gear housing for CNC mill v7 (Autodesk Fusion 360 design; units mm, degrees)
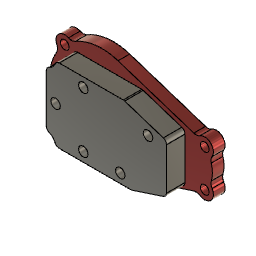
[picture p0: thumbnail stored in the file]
description: Gear Housing Assembly
derived_base_feature "Derived Base Feature1"
derived_base_feature "Derived Base Feature1" bodies "Front Housing"
derived_base_feature "Derived Base Feature1" bodies "Front Cover"
derived_base_feature "Derived Base Feature1" bodies "Back Housing"
as_built_joint "As-built1"
offset_faces "OffsetFaces1" distance 5
delete_face "DeleteFace1"
delete_face "DeleteFace2"
sketch "Sketch1" plane through (0, -21, 0) normal (0, -1, 0) x axis (1, 0, 0)
  line L1 (11.1724, 34.2225) -> (63.2283, 17.2281)
  line L2 (63.2283, -17.2281) -> (11.1724, -34.2225)
  arc A1 centre (64.7801, 21.9812) radius 5 clockwise from (67.4836, 17.7752) to (63.2283, 17.2281)
  arc A2 centre (0, 0) radius 36 clockwise from (-18.189, 31.067) to (11.1724, 34.2225)
  arc A3 centre (-20.7152, 35.3819) radius 5 clockwise from (-18.189, 31.067) to (-22.8701, 30.8701)
  arc A4 centre (-25.4558, 25.4558) radius 6 clockwise from (-30.8701, 22.8701) to (-22.8701, 30.8701)
  arc A5 centre (-35.3819, 20.7152) radius 5 clockwise from (-30.8701, 22.8701) to (-31.067, 18.189)
  arc A6 centre (0, 0) radius 36 clockwise from (-31.067, -18.189) to (-31.067, 18.189)
  arc A7 centre (-35.3819, -20.7152) radius 5 clockwise from (-31.067, -18.189) to (-30.8701, -22.8701)
  arc A8 centre (-25.4558, -25.4558) radius 6 clockwise from (-22.8701, -30.8701) to (-30.8701, -22.8701)
  arc A9 centre (-20.7152, -35.3819) radius 5 clockwise from (-22.8701, -30.8701) to (-18.189, -31.067)
  arc A10 centre (0, 0) radius 36 clockwise from (11.1724, -34.2225) to (-18.189, -31.067)
  arc A11 centre (64.7801, -21.9812) radius 5 clockwise from (63.2283, -17.2281) to (67.4836, -17.7752)
  arc A12 centre (70.7279, -12.7279) radius 6 clockwise from (75.774, -9.4818) to (67.4836, -17.7752)
  arc A13 centre (79.979, -6.7767) radius 5 clockwise from (75.774, -9.4818) to (75.201, -5.3035)
  arc A14 centre (58, 0) radius 18 clockwise from (75.201, 5.3035) to (75.201, -5.3035)
  arc A15 centre (79.979, 6.7767) radius 5 clockwise from (75.201, 5.3035) to (75.774, 9.4818)
  arc A16 centre (70.7279, 12.7279) radius 6 clockwise from (67.4836, 17.7752) to (75.774, 9.4818)
  circle C1 centre (70.7279, -12.7279) radius 3
  circle C2 centre (70.7279, 12.7279) radius 3
  circle C3 centre (-25.4558, -25.4558) radius 3
  circle C4 centre (-25.4558, 25.4558) radius 3
  circle C5 centre (0, 0) radius 5.25
  circle C6 centre (0, 0) radius 19.05
  point P1 (0, 0)
  point P34 (0, 0)
  point P35 (0, -19.05)
  point P36 (-19.05, 0)
  point P37 (0, 19.05)
  point P38 (44.45, 12.7)
  point P39 (25.4, -19.05)
  coincident P1 P34
  coincident C6 P35
  coincident C6 P36
  coincident C6 P37
  vertical P34 P35
  horizontal P1 P36
  vertical P1 P37
  dimension "d2" diameter C6 = 38.1
  dimension "d3" distance P1 P38 = 44.45
  dimension "d4" distance P1 P38 = 12.7
  dimension "d5" distance P34 P39 = 25.4
  dimension "d6" distance P34 P39 = 19.05
hole "Hole1" HoleDepth 5.715 HoleDiameter 5.1308 TipAngle 118
ground "Ground1"
ground "Ground2"
ground "Ground3"
ground "Ground4"
position "Position1"
sketch "Sketch1" plane through (0, 0, 0) normal (0, 1, 0) x axis (1, 0, 0)
  line L1 (57.15, -25.4) -> (-25.4, -25.4)
  line L2 (57.15, 25.4) -> (57.15, -25.4)
  line L3 (-25.4, 25.4) -> (57.15, 25.4)
  line L4 (-25.4, -25.4) -> (-25.4, 25.4)
  line L5 (11.1724, -34.2225) -> (63.2283, -17.2281)
  line L6 (63.2283, 17.2281) -> (11.1724, 34.2225)
  line L7 (10.1871, -31.2042) -> (62.243, -14.2098)
  line L8 (62.7357, 15.719) -> (10.6797, 32.7134)
  circle C1 centre (-25.4558, -25.4558) radius 3
  circle C2 centre (-25.4558, 25.4558) radius 3
  circle C3 centre (-25.4558, -25.4558) radius 6.35
  circle C4 centre (-25.4558, 25.4558) radius 6.35
  point P1 (0, 0)
  horizontal L1
  vertical L2
  horizontal L3
  vertical L4
  concentric C1 C3
  concentric C2 C4
  equal C3 C4
  dimension "d10" distance P1 L1 = 25.4
  dimension "d11" distance P1 L3 = 25.4 (= "d10")
  dimension "d12" distance P1 L2 = 57.15
  dimension "d13" distance P1 L4 = 25.4
  dimension "d14" diameter C3 = 12.7
  dimension "d15" = 3.175
  dimension "d16" = 1.5875
extrude "Extrude1" new body sketch "Sketch1" profile of L1 L2 L3 L4 C3 C4 L7 L8 against normal blind 12.7
fillet "Fillet1" radius 3.175
hole "Hole1" HoleDepth 12.7 HoleDiameter 6.477 TipAngle 118
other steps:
thread "Thread1"
create_component "CreateComponent1"
create_component "CreateComponent5"
create_component "CreateComponent1"
create_component "CreateComponent2"
create_component "CreateComponent3"
named bodies: "Back Housing", "Front Cover", "Front Housing"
